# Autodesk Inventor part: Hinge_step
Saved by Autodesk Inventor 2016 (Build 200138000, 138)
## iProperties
Created: 2016-01
Part Number: Hinge_step
Material: Generic
Document SubType Name: Modeling
Designer: John
Density: 1 g/cm^3
Appearance: Default
Author: John
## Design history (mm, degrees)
feature "Base1"
feature "Base2"
feature "REVOLVE1" [Base]
body "Solid2"
body "Solid3"
body "Solid1"
